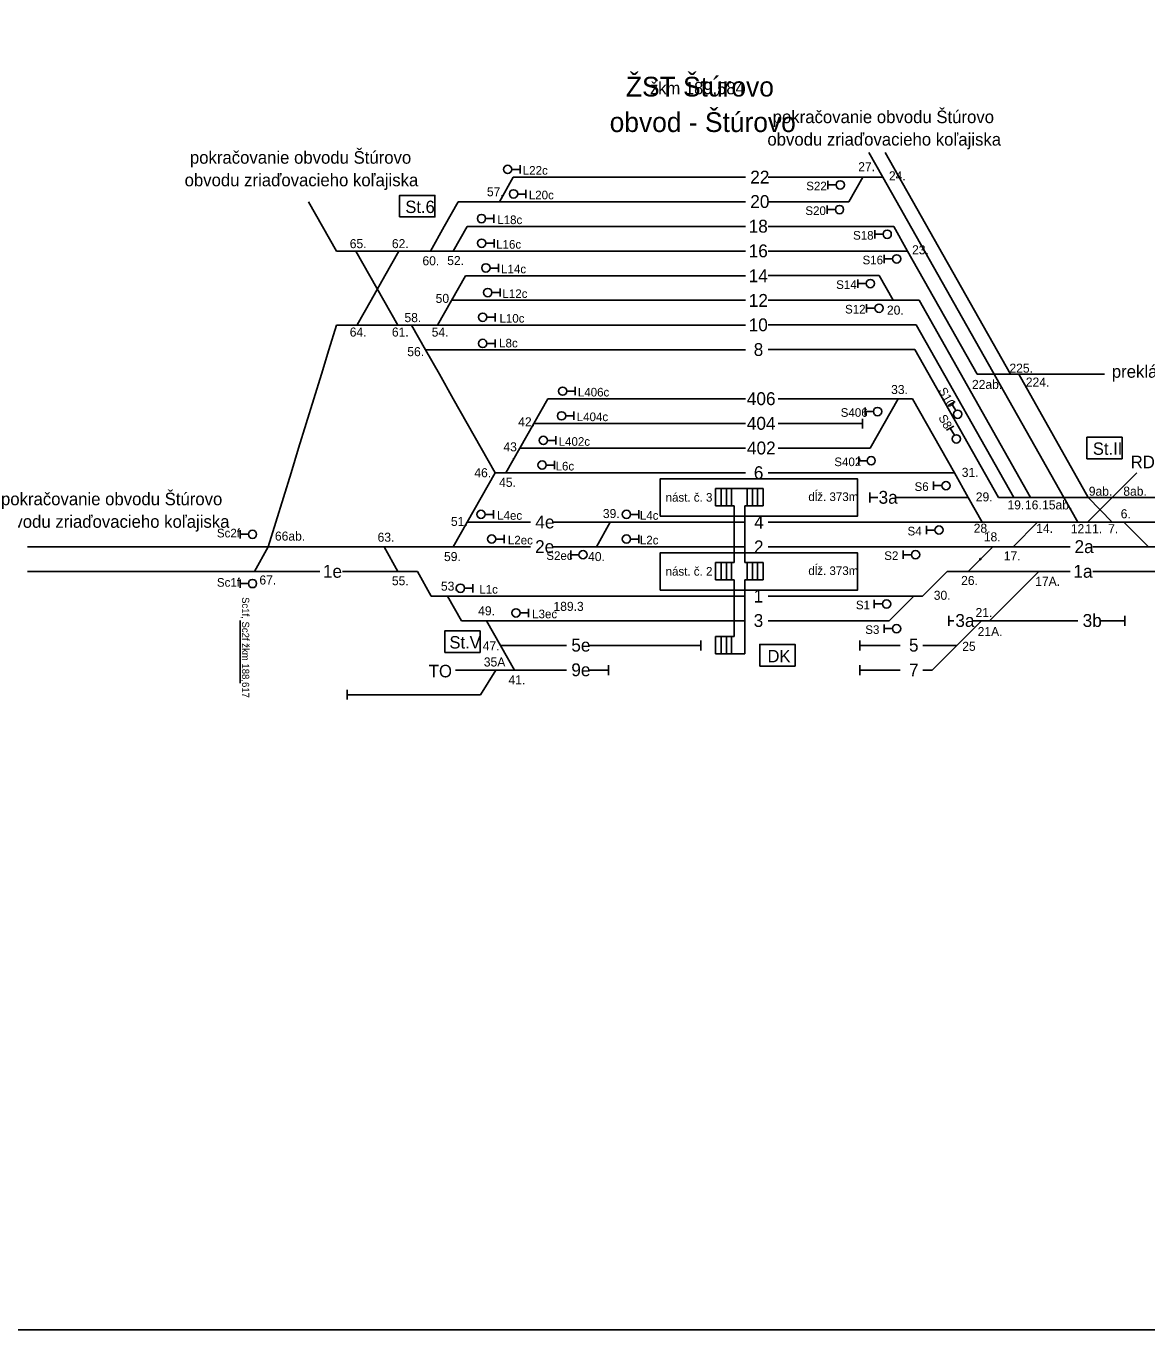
# Model space of a CAD drawing. Extents: x -119 to 851, y -238 to 59.
# Drawn here: x 557.3 to 648.2, y -238 to -132.3 of the extents above; entities that cross this region are included whole.
import ezdxf

# ---------------------------------------------------------------- set-up
doc = ezdxf.new("R2010")
doc.units = 0
for name, color, linetype in [('budova', 7, 'Continuous'), ('Level 2', 7, 'Continuous'), ('Level 33', 7, 'Continuous'), ('nastupistia', 7, 'Continuous'), ('netlač', 7, 'Continuous'), ('popisky navestidla', 7, 'Continuous'), ('popisky stanic a zastavok', 7, 'Continuous'), ('PU_navestidla', 7, 'Continuous'), ('PU_oznacenie navestidiel', 7, 'Continuous'), ('PU_podchod', 7, 'Continuous'), ('PU_stan_kolaje', 7, 'Continuous'), ('PU_vlecky', 7, 'Continuous'), ('schema_km0-1_0-2', 7, 'Continuous')]:
    doc.layers.add(name, color=color, linetype=linetype)

msp = doc.modelspace()

# ---------------------------------------------------------------- linework, layer by layer
at = {"layer": 'budova'}
for points in [[(587.6, -147.74), (590.46, -147.74), (590.46, -145.99), (587.6, -145.99)], [(643.36, -167.35), (646.22, -167.35), (646.22, -165.6), (643.36, -165.6)], [(591.26, -183.06), (594.13, -183.06), (594.13, -181.31), (591.26, -181.31)], [(616.82, -184.16), (619.69, -184.16), (619.69, -182.41), (616.82, -182.41)]]:
    msp.add_lwpolyline(points, close=True, dxfattribs=at)
at = {"layer": 'Level 2'}
for p, q in [((582.27, -144.57), (582.27, -144.57)), ((644.8, -160.5), (635.84, -160.5)), ((637.85, -160.5), (637.75, -160.5)), ((625.15, -164.9), (625.15, -164.1)), ((625.75, -170.9), (625.75, -170.1)), ((626.4, -170.5), (625.75, -170.5)), ((633.74, -170.5), (627.92, -170.5)), ((650.45, -170.5), (641.91, -170.5)), ((632.15, -180.89), (632.15, -180.09)), ((632.15, -180.49), (632.58, -180.49)), ((634.15, -180.49), (642.64, -180.49)), ((646.44, -180.49), (644.48, -180.49)), ((646.44, -180.89), (646.44, -180.09)), ((595.78, -182.49), (601.15, -182.49)), ((602.99, -182.49), (612.05, -182.49)), ((612.05, -182.89), (612.05, -182.09)), ((624.95, -182.89), (624.95, -182.09)), ((628.22, -182.49), (624.95, -182.49)), ((632.81, -182.49), (630.06, -182.49)), ((596.91, -184.49), (592.13, -184.49)), ((601.15, -184.49), (596.91, -184.49)), ((604.55, -184.49), (602.99, -184.49)), ((604.55, -184.89), (604.55, -184.09)), ((624.95, -184.89), (624.95, -184.09)), ((628.22, -184.49), (624.95, -184.49)), ((630.81, -184.49), (630.06, -184.49)), ((583.35, -186.89), (583.35, -186.09)), ((594.15, -186.49), (583.35, -186.49))]:
    msp.add_line(p, q, dxfattribs=at)
for points in [[(596.83, -167.34), (596.85, -167.31)], [(595.4, -184.49), (594.15, -186.49)]]:
    msp.add_lwpolyline(points, dxfattribs=at)
at = {"layer": 'nastupistia'}
for points in [[(608.73, -172), (624.76, -172), (624.76, -168.99), (608.73, -168.99)], [(608.73, -178), (624.76, -178), (624.76, -174.99), (608.73, -174.99)]]:
    msp.add_lwpolyline(points, close=True, dxfattribs=at)
at = {"layer": 'netlač'}
for p, q in [((596.82, -144.51), (615.65, -144.51)), ((617.49, -144.51), (626.8, -144.51)), ((592.35, -146.51), (615.65, -146.51)), ((617.49, -146.51), (624.06, -146.51)), ((593.08, -148.51), (615.65, -148.51)), ((627.69, -148.51), (617.49, -148.51)), ((587.54, -150.51), (582.47, -150.51)), ((587.54, -150.51), (615.65, -150.51)), ((628.82, -150.51), (617.49, -150.51)), ((592.94, -152.51), (615.65, -152.51)), ((617.49, -152.5), (626.52, -152.5)), ((591.81, -154.5), (615.65, -154.5)), ((617.49, -154.5), (629.75, -154.5)), ((582.48, -156.51), (588.56, -156.51)), ((588.56, -156.51), (615.65, -156.51)), ((617.49, -156.5), (629.52, -156.5)), ((589.69, -158.51), (615.65, -158.51)), ((617.49, -158.5), (629.41, -158.5)), ((635.84, -160.5), (634.47, -160.5)), ((599.61, -162.5), (615.65, -162.5)), ((628.05, -162.5), (618.3, -162.5)), ((629.22, -162.5), (628.05, -162.5)), ((598.48, -164.5), (615.65, -164.5)), ((625.15, -164.5), (618.3, -164.5)), ((597.35, -166.5), (615.65, -166.5)), ((625.79, -166.5), (618.3, -166.5)), ((595.34, -168.5), (615.65, -168.5)), ((617.49, -168.5), (632.61, -168.5)), ((643.48, -170.5), (636.19, -170.5)), ((593.08, -172.5), (598.23, -172.5)), ((600.07, -172.5), (615.65, -172.5)), ((639.37, -172.49), (617.49, -172.49)), ((639.37, -172.49), (664.68, -172.49)), ((557.39, -174.49), (581.13, -174.49)), ((581.13, -174.49), (598.23, -174.49)), ((600.07, -174.49), (615.65, -174.49)), ((635.72, -174.49), (617.49, -174.49)), ((642, -174.49), (635.72, -174.49)), ((664.74, -174.49), (643.84, -174.49)), ((581.13, -176.49), (557.39, -176.49)), ((589.04, -176.49), (582.96, -176.49)), ((632.02, -176.49), (642, -176.49)), ((643.84, -176.49), (664.74, -176.49)), ((590.17, -178.49), (615.65, -178.49)), ((630.02, -178.49), (617.49, -178.49)), ((615.65, -180.49), (592.62, -180.49)), ((627.32, -180.49), (617.49, -180.49))]:
    msp.add_line(p, q, dxfattribs=at)
at = {"layer": 'popisky navestidla'}
msp.add_line((574.66, -180.47), (574.66, -185.56), dxfattribs=at)
msp.add_lwpolyline([(-118.95, -238.01), (851.05, -238.01), (851.05, 58.99), (-118.95, 58.99)], close=True, dxfattribs=at)
at = {"layer": 'PU_navestidla'}
for p, q in [((597.37, -143.54), (597.37, -144.21)), ((597.37, -143.88), (596.69, -143.88)), ((622.35, -145.48), (622.35, -144.81)), ((597.85, -145.88), (597.18, -145.88)), ((597.85, -145.54), (597.85, -146.21)), ((622.35, -145.14), (623.02, -145.14)), ((622.28, -147.48), (622.28, -146.81)), ((595.24, -147.87), (594.57, -147.87)), ((595.24, -147.54), (595.24, -148.21)), ((622.28, -147.14), (622.95, -147.14)), ((626.16, -149.48), (626.16, -148.81)), ((595.26, -149.87), (594.59, -149.87)), ((595.26, -149.53), (595.26, -150.21)), ((626.16, -149.14), (626.83, -149.14)), ((626.92, -151.48), (626.92, -150.81)), ((626.92, -151.14), (627.59, -151.14)), ((595.61, -151.88), (594.94, -151.88)), ((595.61, -151.54), (595.61, -152.21)), ((624.78, -153.48), (624.78, -152.8)), ((624.78, -153.14), (625.45, -153.14)), ((595.76, -153.87), (595.08, -153.87)), ((595.76, -153.53), (595.76, -154.2)), ((625.49, -155.48), (625.49, -154.8)), ((625.49, -155.14), (626.16, -155.14)), ((595.34, -155.87), (594.67, -155.87)), ((595.34, -155.54), (595.34, -156.21)), ((595.34, -158), (594.67, -158)), ((595.34, -157.67), (595.34, -158.34)), ((601.84, -161.53), (601.84, -162.2)), ((601.84, -161.87), (601.17, -161.87)), ((632.1, -163.03), (632.68, -162.7)), ((601.74, -163.87), (601.07, -163.87)), ((601.74, -163.53), (601.74, -164.2)), ((625.37, -163.85), (625.37, -163.18)), ((625.37, -163.51), (626.04, -163.51)), ((632.39, -162.87), (632.72, -163.45)), ((631.98, -165.03), (632.57, -164.7)), ((632.28, -164.87), (632.61, -165.45)), ((600.27, -165.87), (599.6, -165.87)), ((600.27, -165.53), (600.27, -166.2)), ((600.17, -167.86), (599.5, -167.86)), ((600.17, -167.53), (600.17, -168.2)), ((624.85, -167.85), (624.85, -167.18)), ((624.85, -167.51), (625.52, -167.51)), ((630.92, -169.86), (630.92, -169.19)), ((630.92, -169.52), (631.59, -169.52)), ((595.21, -171.86), (594.54, -171.86)), ((595.21, -171.52), (595.21, -172.2)), ((607.01, -171.86), (606.34, -171.86)), ((607.01, -171.52), (607.01, -172.2)), ((574.65, -173.14), (574.65, -173.81)), ((630.35, -173.47), (630.35, -172.79)), ((630.35, -173.13), (631.02, -173.13)), ((574.65, -173.48), (575.32, -173.48)), ((596.08, -173.86), (595.41, -173.86)), ((596.08, -173.52), (596.08, -174.19)), ((607.01, -173.86), (606.34, -173.86)), ((607.01, -173.52), (607.01, -174.19)), ((601.48, -175.47), (601.48, -174.79)), ((601.48, -175.13), (602.15, -175.13)), ((628.45, -175.47), (628.45, -174.79)), ((628.45, -175.13), (629.13, -175.13)), ((574.65, -177.14), (574.65, -177.81)), ((574.65, -177.47), (575.32, -177.47)), ((593.53, -177.52), (593.53, -178.19)), ((593.53, -177.86), (592.86, -177.86)), ((598.05, -179.52), (598.05, -180.19)), ((626.1, -179.46), (626.1, -178.79)), ((626.1, -179.13), (626.77, -179.13)), ((598.05, -179.85), (597.38, -179.85)), ((626.92, -181.46), (626.92, -180.79)), ((626.92, -181.13), (627.59, -181.13))]:
    msp.add_line(p, q, dxfattribs=at)
for centre in [(596.36, -143.88), (623.35, -145.14), (596.84, -145.87), (623.29, -147.14), (594.24, -147.87), (627.16, -149.14), (594.25, -149.87), (627.93, -151.14), (594.6, -151.87), (625.79, -153.14), (594.75, -153.87), (626.5, -155.14), (594.34, -155.87), (594.34, -158), (600.83, -161.87), (600.74, -163.87), (626.38, -163.52), (632.88, -163.74), (599.26, -165.86), (632.77, -165.74), (599.16, -167.86), (625.86, -167.51), (631.93, -169.53), (594.2, -171.86), (606, -171.86), (575.66, -173.48), (631.36, -173.13), (595.07, -173.86), (606, -173.86), (602.48, -175.13), (629.46, -175.13), (575.66, -177.47), (592.53, -177.85), (597.04, -179.85), (627.11, -179.13), (627.92, -181.13)]:
    msp.add_circle(centre, 0.336, dxfattribs=at)
at = {"layer": 'PU_podchod'}
for p, q in [((613.24, -169.76), (613.24, -171.17)), ((614.73, -169.76), (613.24, -169.76)), ((613.68, -169.76), (613.68, -171.17)), ((614.11, -169.76), (614.11, -171.17)), ((614.54, -169.76), (614.54, -171.17)), ((617.09, -169.76), (614.73, -169.76)), ((615.79, -169.76), (615.79, -171.17)), ((616.22, -169.76), (616.22, -171.17)), ((616.65, -169.76), (616.65, -171.17)), ((617.09, -169.76), (617.09, -171.17)), ((614.73, -171.17), (613.24, -171.17)), ((614.73, -171.17), (614.73, -175.76)), ((615.6, -171.17), (615.6, -175.76)), ((617.09, -171.17), (615.6, -171.17)), ((613.24, -175.76), (613.24, -177.17)), ((614.73, -175.76), (613.24, -175.76)), ((613.68, -175.76), (613.68, -177.17)), ((614.11, -175.76), (614.11, -177.17)), ((614.54, -175.76), (614.54, -177.17)), ((617.09, -175.76), (615.6, -175.76)), ((615.79, -175.76), (615.79, -177.17)), ((616.22, -175.76), (616.22, -177.17)), ((616.65, -175.76), (616.65, -177.17)), ((617.09, -175.76), (617.09, -177.17)), ((614.73, -177.17), (613.24, -177.17)), ((614.73, -177.17), (614.73, -181.76)), ((617.09, -177.17), (615.6, -177.17)), ((615.6, -177.17), (615.6, -183.16)), ((613.24, -181.76), (613.24, -183.16)), ((614.73, -181.76), (613.24, -181.76)), ((613.68, -181.76), (613.68, -183.16)), ((614.11, -181.76), (614.11, -183.16)), ((614.54, -181.76), (614.54, -183.16)), ((615.6, -183.16), (613.24, -183.16))]:
    msp.add_line(p, q, dxfattribs=at)
at = {"layer": 'PU_stan_kolaje'}
for p, q in [((628.82, -150.51), (634.47, -160.5)), ((643.48, -170.5), (645.42, -172.49))]:
    msp.add_line(p, q, dxfattribs=at)
for points in [[(625.67, -142.51), (626.8, -144.51)], [(627, -142.51), (637.17, -160.5)], [(596.82, -144.51), (595.69, -146.51)], [(624.06, -146.51), (625.19, -144.51)], [(626.8, -144.51), (641.49, -170.5)], [(580.21, -146.51), (581.34, -148.51)], [(592.35, -146.51), (591.22, -148.51)], [(581.34, -148.51), (582.47, -150.51)], [(591.22, -148.51), (590.09, -150.51)], [(593.08, -148.51), (591.95, -150.51)], [(627.69, -148.51), (628.82, -150.51)], [(584.05, -150.51), (585.18, -152.51)], [(587.54, -150.51), (586.41, -152.51)], [(585.18, -152.51), (586.31, -154.51)], [(586.41, -152.51), (585.28, -154.5)], [(592.94, -152.51), (591.81, -154.51)], [(626.52, -152.5), (627.65, -154.5)], [(585.28, -154.5), (584.15, -156.5)], [(586.31, -154.51), (587.44, -156.51)], [(591.81, -154.51), (590.68, -156.51)], [(629.75, -154.5), (638.79, -170.5)], [(581.86, -158.51), (582.48, -156.51)], [(588.56, -156.51), (589.69, -158.51)], [(629.52, -156.5), (637.43, -170.5)], [(581.25, -160.5), (581.86, -158.51)], [(589.69, -158.51), (590.82, -160.5)], [(629.41, -158.5), (636.19, -170.5)], [(580.63, -162.5), (581.25, -160.5)], [(590.82, -160.5), (591.95, -162.5)], [(637.83, -160.5), (643.48, -170.5)], [(580.02, -164.5), (580.63, -162.5)], [(591.95, -162.5), (593.08, -164.5)], [(598.48, -164.5), (599.61, -162.5)], [(626.92, -164.5), (628.05, -162.5)], [(629.22, -162.5), (630.35, -164.5)], [(579.4, -166.5), (580.02, -164.5)], [(593.08, -164.5), (594.21, -166.5)], [(597.35, -166.5), (598.48, -164.5)], [(625.79, -166.5), (626.92, -164.5)], [(630.35, -164.5), (631.48, -166.5)], [(578.79, -168.5), (579.4, -166.5)], [(594.21, -166.5), (595.34, -168.5)], [(596.22, -168.5), (597.35, -166.5)], [(631.48, -166.5), (632.61, -168.5)], [(578.17, -170.5), (578.79, -168.5)], [(594.21, -170.5), (595.34, -168.5)], [(632.61, -168.5), (633.74, -170.5)], [(647.42, -168.49), (645.42, -170.49)], [(577.56, -172.5), (578.17, -170.5)], [(593.08, -172.5), (594.21, -170.5)], [(633.74, -170.5), (634.87, -172.49)], [(641.49, -170.5), (642.62, -172.49)], [(645.42, -170.49), (643.42, -172.49)], [(576.94, -174.49), (577.56, -172.5)], [(591.95, -174.49), (593.08, -172.5)], [(603.56, -174.49), (604.69, -172.5)], [(639.37, -172.49), (637.37, -174.49)], [(646.37, -172.49), (648.37, -174.49)], [(575.81, -176.49), (576.94, -174.49)], [(586.33, -174.49), (587.46, -176.49)], [(635.72, -174.49), (633.72, -176.49)], [(589.04, -176.49), (590.17, -178.49)], [(632.02, -176.49), (630.02, -178.49)], [(639.47, -176.49), (637.47, -178.49)], [(591.49, -178.49), (592.62, -180.49)], [(629.32, -178.49), (627.32, -180.49)], [(637.47, -178.49), (635.47, -180.49)], [(594.65, -180.49), (595.78, -182.49)], [(634.81, -180.49), (632.81, -182.49)], [(595.78, -182.49), (596.91, -184.49)], [(632.81, -182.49), (630.81, -184.49)]]:
    msp.add_lwpolyline(points, dxfattribs=at)
at = {"layer": 'schema_km0-1_0-2'}
msp.add_circle((634.72, -175.49), 0.0502, dxfattribs=at)

# ---------------------------------------------------------------- texts
at = {"layer": 'budova'}
for s, p in [('St.6', (588.06, -147.42)), ('St.II', (643.85, -167.03)), ('St.V', (591.64, -182.74)), ('DK', (617.45, -183.86))]:
    msp.add_text(s, height=1.004, dxfattribs=at).set_placement(p)
at = {"layer": 'Level 2'}
for s, height, p in [('27.', 0.733, (624.81, -144.03)), ('22', 1.044, (616.05, -145.03)), ('24.', 0.733, (627.3, -144.77)), ('57.', 0.733, (594.68, -146.06)), ('20', 1.044, (616.05, -147.01)), ('18', 1.044, (615.92, -149.01)), ('65.', 0.733, (583.55, -150.27)), ('62.', 0.733, (586.97, -150.27)), ('16', 1.044, (615.92, -151.01)), ('23.', 0.733, (629.18, -150.77)), ('60.', 0.733, (589.45, -151.66)), ('52.', 0.733, (591.46, -151.64)), ('14', 1.044, (615.92, -153.03)), ('50.', 0.733, (590.52, -154.71)), ('12', 1.044, (615.93, -155.03)), ('20.', 0.733, (627.14, -155.66)), ('58.', 0.733, (587.99, -156.27)), ('10', 1.044, (615.92, -157.01)), ('64.', 0.733, (583.55, -157.44)), ('61.', 0.733, (586.97, -157.44)), ('54.', 0.733, (590.2, -157.44)), ('56.', 0.733, (588.22, -159.03)), ('8', 1.04, (616.33, -159.01)), ('225.', 0.733, (637.08, -160.37)), ('33.', 0.733, (627.48, -162.1)), ('22ab.', 0.733, (634.04, -161.69)), ('224.', 0.733, (638.41, -161.5)), ('406', 1.044, (615.77, -163)), ('42.', 0.733, (597.22, -164.72)), ('404', 1.044, (615.77, -165)), ('43.', 0.733, (596.02, -166.75)), ('402', 1.044, (615.78, -167)), ('46.', 0.733, (593.66, -168.85)), ('6', 1.04, (616.34, -169)), ('31.', 0.733, (633.21, -168.82)), ('45.', 0.733, (595.67, -169.63)), ('3a', 1.044, (626.46, -171)), ('29.', 0.733, (634.35, -170.81)), ('9ab.', 0.733, (643.52, -170.35)), ('8ab.', 0.733, (646.32, -170.35)), ('19.', 0.733, (636.92, -171.46)), ('16.', 0.733, (638.34, -171.46)), ('15ab.', 0.733, (639.73, -171.46)), ('51.', 0.733, (591.76, -172.8)), ('4e', 1.044, (598.61, -173)), ('39.', 0.733, (604.09, -172.16)), ('4', 1.04, (616.37, -173.02)), ('6.', 0.733, (646.11, -172.18)), ('66ab.', 0.733, (577.48, -173.99)), ('63.', 0.733, (585.81, -174.08)), ('28.', 0.733, (634.18, -173.35)), ('18.', 0.733, (635, -174.05)), ('14.', 0.733, (639.25, -173.36)), ('12.', 0.733, (642.06, -173.39)), ('11.', 0.733, (643.24, -173.39)), ('7.', 0.733, (645.09, -173.39)), ('2e', 1.044, (598.59, -175)), ('2', 1.04, (616.35, -175.02)), ('2a', 1.044, (642.36, -175)), ('59.', 0.733, (591.2, -175.65)), ('40.', 0.733, (602.89, -175.65)), ('17.', 0.733, (636.62, -175.6)), ('1e', 1.044, (581.37, -177)), ('1a', 1.044, (642.27, -177)), ('67.', 0.733, (576.22, -177.55)), ('55.', 0.733, (586.97, -177.61)), ('53.', 0.733, (590.95, -178.05)), ('26.', 0.733, (633.16, -177.59)), ('17A.', 0.733, (639.17, -177.66)), ('1', 1.04, (616.32, -179.01)), ('30.', 0.733, (630.94, -178.79)), ('49.', 0.733, (593.97, -180.05)), ('21.', 0.733, (634.33, -180.19)), ('3', 1.04, (616.33, -180.99)), ('3a', 1.044, (632.69, -180.99)), ('3b', 1.044, (643.02, -180.99)), ('21A.', 0.733, (634.5, -181.73)), ('47.', 0.733, (594.34, -182.9)), ('5e', 1.044, (601.53, -182.99)), ('5', 1.04, (628.93, -182.99)), ('25', 0.733, (633.25, -182.93)), ('35A', 0.733, (594.43, -184.2)), ('9e', 1.044, (601.53, -184.99)), ('7', 1.04, (628.93, -185.01)), ('41.', 0.733, (596.43, -185.65))]:
    msp.add_text(s, height=height, dxfattribs=at).set_placement(p)
at = {"layer": 'Level 33'}
msp.add_text('189.3', height=0.733, dxfattribs=at).set_placement((600.08, -179.69))
at = {"layer": 'nastupistia'}
for s, p in [('nást. č. 3', (609.18, -170.83)), ('dĺž. 373m', (620.76, -170.78)), ('nást. č. 2', (609.18, -176.83)), ('dĺž. 373m', (620.76, -176.78))]:
    msp.add_text(s, height=0.7, dxfattribs=at).set_placement(p)
at = {"layer": 'popisky navestidla'}
msp.add_text('Sc1f, Sc2f žkm 188,617', height=0.5793, rotation=270, dxfattribs=at).set_placement((574.81, -178.57))
at = {"layer": 'popisky stanic a zastavok'}
for s, height, p in [('ŽST Štúrovo', 1.6, (605.96, -137.97)), ('žkm 189,584', 1.0044, (607.91, -137.79)), ('obvod - Štúrovo', 1.6, (604.64, -140.85))]:
    msp.add_text(s, height=height, dxfattribs=at).set_placement(p)
at = {"layer": 'PU_oznacenie navestidiel'}
for s, p in [('L22c', (597.59, -144.31)), ('S22', (620.59, -145.58)), ('L20c', (598.08, -146.31)), ('S20', (620.52, -147.58)), ('L18c', (595.52, -148.32)), ('S18', (624.39, -149.58)), ('L16c', (595.43, -150.31)), ('S16', (625.16, -151.58)), ('L14c', (595.83, -152.31)), ('S14', (623.02, -153.58)), ('L12c', (595.94, -154.31)), ('S12', (623.74, -155.57)), ('L10c', (595.7, -156.31)), ('L8c', (595.67, -158.32)), ('L406c', (602.06, -162.3)), ('L404c', (601.97, -164.3)), ('S406', (623.39, -163.95)), ('L402c', (600.5, -166.3)), ('L6c', (600.25, -168.3)), ('S402', (622.87, -167.95)), ('S6', (629.38, -169.96)), ('L4ec', (595.51, -172.3)), ('L4c', (607.09, -172.3)), ('Sc2f', (572.77, -173.73)), ('S4', (628.81, -173.57)), ('L2ec', (596.38, -174.3)), ('L2c', (607.09, -174.3)), ('S2ec', (599.5, -175.56)), ('S2', (626.92, -175.56)), ('Sc1f', (572.77, -177.73)), ('L1c', (594.06, -178.29)), ('L3ec', (598.35, -180.29)), ('S1', (624.62, -179.56)), ('S3', (625.38, -181.56))]:
    msp.add_text(s, height=0.7, dxfattribs=at).set_placement(p)
for s, p in [('S10', (631.29, -161.81)), ('S8', (631.29, -164.01))]:
    msp.add_text(s, height=0.7, rotation=299.4841, dxfattribs=at).set_placement(p)
at = {"layer": 'PU_vlecky'}
for s, p in [('pokračovanie obvodu Štúrovo ', (617.87, -140.13)), ('obvodu zriaďovacieho koľajiska', (617.44, -141.95)), ('pokračovanie obvodu Štúrovo ', (570.58, -143.42)), ('obvodu zriaďovacieho koľajiska', (570.15, -145.25)), ('prekládkové rampy', (645.39, -160.78)), ('RD', (646.92, -168.12)), ('pokračovanie obvodu Štúrovo ', (555.25, -171.12)), ('obvodu zriaďovacieho koľajiska', (554.83, -172.95)), ('TO', (589.96, -185.08))]:
    msp.add_text(s, height=1.015, dxfattribs=at).set_placement(p)

doc.saveas('drawing.dxf')
